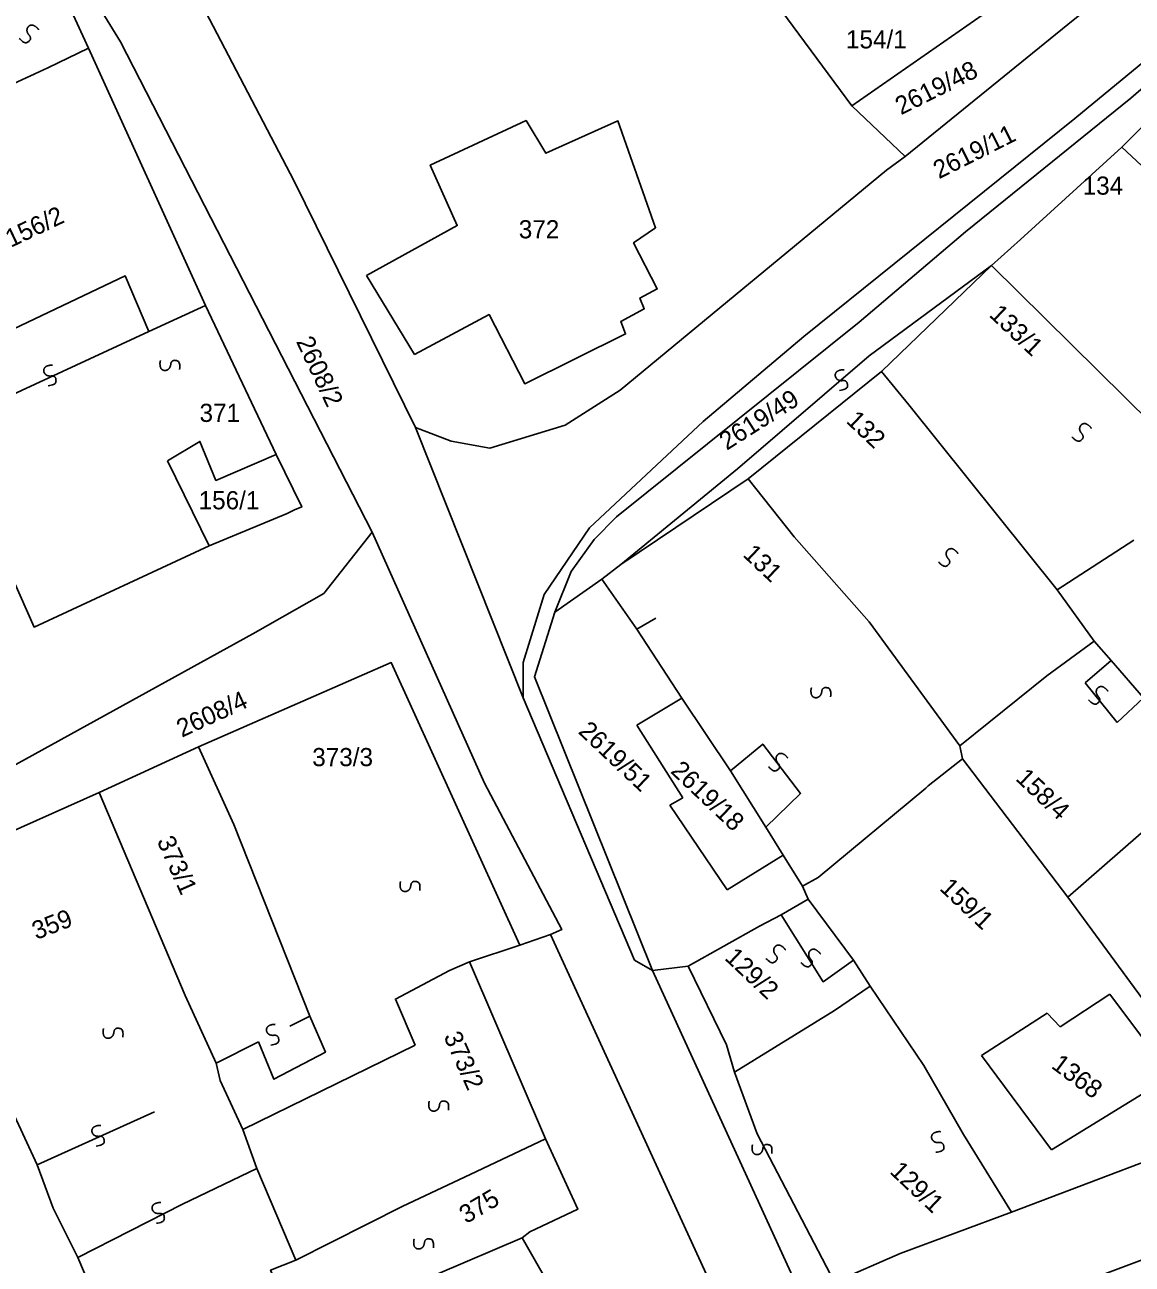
# Model space of a CAD drawing. Extents: x -581999 to -572728, y -1219553 to -1212032.
# Drawn here: x -577580.3 to -577458.4, y -1215689.6 to -1215553.2 of the extents above; entities that cross this region are included whole.
import ezdxf

# ---------------------------------------------------------------- set-up
doc = ezdxf.new("R2010")
doc.units = 0
for name, color, linetype in [('Vrstva 1', 7, 'Continuous'), ('Vrstva 2', 7, 'Continuous'), ('Vrstva 4', 7, 'Continuous'), ('Vrstva 6', 7, 'Continuous')]:
    doc.layers.add(name, color=color, linetype=linetype)

msp = doc.modelspace()

# ---------------------------------------------------------------- linework, layer by layer
at = {"layer": 'Vrstva 1'}
for p, q in [((-577458.52, -1215561.261), (-577448.646, -1215552.634)), ((-577459.515, -1215566.648), (-577447.034, -1215554.113)), ((-577476.745, -1215575.972), (-577458.52, -1215561.261)), ((-577489.259, -1215562.107), (-577483.372, -1215567.684)), ((-577488.453, -1215585.918), (-577476.745, -1215575.972)), ((-577485.982, -1215591.353), (-577473.873, -1215579.702)), ((-577515.182, -1215607.363), (-577488.453, -1215585.918)), ((-577500.672, -1215603.163), (-577485.982, -1215591.353)), ((-577514.699, -1215612.591), (-577500.672, -1215603.163)), ((-577500.672, -1215603.163), (-577495.592, -1215609.547)), ((-577517.611, -1215609.849), (-577515.182, -1215607.363)), ((-577520.152, -1215613.372), (-577517.611, -1215609.849)), ((-577521.967, -1215617.844), (-577520.152, -1215613.372)), ((-577516.777, -1215614.222), (-577514.699, -1215612.591)), ((-577507.962, -1215627.302), (-577512.932, -1215630.306)), ((-577512.932, -1215630.306), (-577507.851, -1215638.283)), ((-577507.851, -1215638.283), (-577509.287, -1215639.112)), ((-577509.287, -1215639.112), (-577502.992, -1215648.436)), ((-577502.992, -1215648.436), (-577496.806, -1215644.603)), ((-577489.076, -1215656.174), (-577494.066, -1215649.44)), ((-577507.266, -1215656.833), (-577503.039, -1215665.479)), ((-577466.299, -1215663.519), (-577460.844, -1215659.907)), ((-577460.844, -1215659.907), (-577454.106, -1215668.936)), ((-577502.157, -1215668.483), (-577491.155, -1215661.717)), ((-577474.962, -1215666.679), (-577467.742, -1215662.014)), ((-577467.742, -1215662.014), (-577466.299, -1215663.519)), ((-577503.039, -1215665.479), (-577502.157, -1215668.483)), ((-577467.261, -1215677.063), (-577474.962, -1215666.679)), ((-577454.106, -1215668.936), (-577467.261, -1215677.063))]:
    msp.add_line(p, q, dxfattribs=at)
for points in [[(-577068.022, -1215163.106), (-577076.012, -1215171.394), (-577092.817, -1215198.932), (-577107.282, -1215215.508), (-577162.965, -1215281.857), (-577201.26, -1215325.168), (-577221.372, -1215346.69), (-577272.951, -1215402.049), (-577277.91, -1215407.931), (-577301.723, -1215433.783), (-577314.534, -1215448.22), (-577343.272, -1215476.19), (-577359.94, -1215491.697), (-577381.842, -1215506.802), (-577421.443, -1215531.966), (-577436.182, -1215542.126), (-577449.269, -1215550.815), (-577464.697, -1215563.514), (-577494.524, -1215587.485), (-577505.622, -1215596.863)], [(-577542.069, -1215609.057), (-577569.787, -1215555.06), (-577595.081, -1215514.025)], [(-577537.306, -1215597.532), (-577533.369, -1215599.008), (-577529.099, -1215599.81), (-577520.833, -1215597.27), (-577514.772, -1215593.393), (-577485.431, -1215569.198), (-577483.372, -1215567.684), (-577465.456, -1215553.156), (-577437.567, -1215530.67), (-577426.685, -1215523.986)], [(-577537.306, -1215597.532), (-577550.668, -1215570.395), (-577570.197, -1215533.019)], [(-577573.298, -1215555.752), (-577579.998, -1215541.197), (-577595.01, -1215547.623)], [(-577474.061, -1215551.543), (-577489.259, -1215562.107), (-577502.181, -1215544.592)], [(-577577.773, -1215557.917), (-577573.298, -1215555.752)], [(-577560.411, -1215584.076), (-577573.298, -1215555.752)], [(-577585.632, -1215564.592), (-577584.028, -1215560.775), (-577577.773, -1215557.917)], [(-577542.695, -1215580.767), (-577532.692, -1215575.284), (-577535.667, -1215568.649), (-577525.12, -1215563.72), (-577522.951, -1215567.317), (-577515.008, -1215563.759), (-577510.857, -1215575.52), (-577513.289, -1215577.205), (-577510.683, -1215582.262), (-577512.594, -1215583.273), (-577512.103, -1215584.469), (-577514.706, -1215585.839), (-577514.166, -1215587.22), (-577525.259, -1215592.698), (-577529.185, -1215585.096), (-577537.406, -1215589.48)], [(-577473.873, -1215579.702), (-577470.68, -1215576.809), (-577459.515, -1215566.648)], [(-577456.256, -1215569.707), (-577459.515, -1215566.648)], [(-577590.029, -1215590.689), (-577569.28, -1215580.813), (-577566.67, -1215586.953)], [(-577537.406, -1215589.48), (-577542.695, -1215580.767)], [(-577473.873, -1215579.702), (-577456.24, -1215597.098)], [(-577566.67, -1215586.953), (-577560.411, -1215584.076)], [(-577552.643, -1215600.488), (-577560.411, -1215584.076)], [(-577485.982, -1215591.353), (-577482.98, -1215595.027)], [(-577482.98, -1215595.027), (-577466.627, -1215615.378)], [(-577587.202, -1215596.462), (-577586.184, -1215603.987), (-577579.3, -1215619.493), (-577560.005, -1215610.562)], [(-577525.457, -1215627.283), (-577525.457, -1215623.406), (-577523.115, -1215615.92), (-577518.156, -1215608.568), (-577505.622, -1215596.863)], [(-577525.457, -1215627.283), (-577537.306, -1215597.532)], [(-577564.597, -1215601.184), (-577561.026, -1215599.06), (-577559.268, -1215603.344), (-577552.643, -1215600.488)], [(-577564.597, -1215601.184), (-577560.005, -1215610.562)], [(-577550.608, -1215606.567), (-577549.817, -1215606.259), (-577552.643, -1215600.488)], [(-577551.432, -1215606.992), (-577550.608, -1215606.567)], [(-577560.005, -1215610.562), (-577551.432, -1215606.992)], [(-577555.196, -1215620.24), (-577547.406, -1215615.791), (-577542.069, -1215609.057)], [(-577542.069, -1215609.057), (-577529.703, -1215636.683)], [(-577495.592, -1215609.547), (-577487.332, -1215618.917), (-577477.371, -1215632.563)], [(-577458.187, -1215609.912), (-577466.627, -1215615.378)], [(-577521.967, -1215617.844), (-577516.777, -1215614.222)], [(-577516.777, -1215614.222), (-577512.932, -1215619.739), (-577507.962, -1215627.302), (-577502.615, -1215635.324)], [(-577466.627, -1215615.378), (-577462.585, -1215621.062)], [(-577511.186, -1215657.294), (-577524.197, -1215624.96), (-577521.967, -1215617.844)], [(-577583.13, -1215635.607), (-577555.196, -1215620.24)], [(-577462.585, -1215621.062), (-577467.774, -1215624.843)], [(-577449.892, -1215635.66), (-577457.154, -1215627.301), (-577460.689, -1215623.157), (-577462.585, -1215621.062)], [(-577561.175, -1215632.674), (-577539.962, -1215623.407), (-577525.817, -1215654.531)], [(-577467.774, -1215624.843), (-577477.371, -1215632.563)], [(-577511.186, -1215657.294), (-577513.197, -1215656.157), (-577525.457, -1215627.283)], [(-577572.129, -1215637.719), (-577561.175, -1215632.674)], [(-577557.293, -1215641.237), (-577561.175, -1215632.674)], [(-577477.371, -1215632.563), (-577477.065, -1215633.989)], [(-577477.065, -1215633.989), (-577480.841, -1215636.983)], [(-577465.471, -1215649.214), (-577477.065, -1215633.989)], [(-577502.615, -1215635.324), (-577498.728, -1215641.51)], [(-577529.703, -1215636.683), (-577521.191, -1215652.805), (-577522.437, -1215653.322)], [(-577449.892, -1215635.66), (-577465.471, -1215649.214)], [(-577572.129, -1215637.719), (-577589.417, -1215645.417)], [(-577562.666, -1215660.071), (-577572.129, -1215637.719)], [(-577480.841, -1215636.983), (-577481.122, -1215637.247), (-577492.957, -1215647.069)], [(-577557.293, -1215641.237), (-577548.925, -1215662.317)], [(-577498.728, -1215641.51), (-577496.806, -1215644.603), (-577494.685, -1215648.013)], [(-577492.957, -1215647.069), (-577494.685, -1215648.013)], [(-577494.685, -1215648.013), (-577494.066, -1215649.44), (-577497.052, -1215651.17)], [(-577465.471, -1215649.214), (-577446.895, -1215674.51)], [(-577497.052, -1215651.17), (-577499.409, -1215652.428)], [(-577499.409, -1215652.428), (-577507.266, -1215656.833)], [(-577522.437, -1215653.322), (-577525.817, -1215654.531)], [(-577522.437, -1215653.322), (-577496.282, -1215710.3)], [(-577525.817, -1215654.531), (-577531.339, -1215656.362)], [(-577531.339, -1215656.362), (-577533.538, -1215657.304)], [(-577522.968, -1215675.854), (-577531.339, -1215656.362)], [(-577507.266, -1215656.833), (-577511.186, -1215657.294)], [(-577487.224, -1215659.039), (-577489.076, -1215656.174)], [(-577533.538, -1215657.304), (-577539.509, -1215660.449), (-577537.339, -1215665.521)], [(-577511.186, -1215657.294), (-577494.758, -1215693.186)], [(-577491.155, -1215661.717), (-577487.224, -1215659.039)], [(-577487.224, -1215659.039), (-577481.314, -1215667.761)], [(-577587.122, -1215661.102), (-577578.944, -1215678.684)], [(-577559.251, -1215667.522), (-577562.666, -1215660.071)], [(-577548.925, -1215662.317), (-577547.219, -1215666.279), (-577552.877, -1215669.268), (-577554.582, -1215665.147)], [(-577554.582, -1215665.147), (-577559.251, -1215667.522)], [(-577537.339, -1215665.521), (-577556.305, -1215674.812)], [(-577558.789, -1215669.422), (-577559.251, -1215667.522)], [(-577481.314, -1215667.761), (-577476.966, -1215675.369)], [(-577556.305, -1215674.812), (-577558.789, -1215669.422)], [(-577554.757, -1215679.089), (-577556.305, -1215674.812)], [(-577446.895, -1215674.51), (-577471.684, -1215683.928)], [(-577531.294, -1215679.782), (-577522.968, -1215675.854)], [(-577522.968, -1215675.854), (-577519.428, -1215683.593), (-577524.702, -1215686.068)], [(-577476.966, -1215675.369), (-577471.684, -1215683.928)], [(-577578.944, -1215678.684), (-577577.205, -1215683.467)], [(-577554.757, -1215679.089), (-577550.462, -1215689.214)], [(-577538.677, -1215683.24), (-577531.294, -1215679.782)], [(-577468.038, -1215693.198), (-577433.831, -1215680.339), (-577425.062, -1215680.368), (-577420.535, -1215682.912), (-577418.354, -1215684.817)], [(-577577.205, -1215683.467), (-577574.478, -1215688.919)], [(-577550.462, -1215689.214), (-577538.677, -1215683.24)], [(-577471.684, -1215683.928), (-577483.925, -1215688.476)], [(-577537.566, -1215691.939), (-577534.847, -1215690.688), (-577525.554, -1215686.729)], [(-577524.702, -1215686.068), (-577525.554, -1215686.729)], [(-577525.554, -1215686.729), (-577521.009, -1215694.714)], [(-577483.925, -1215688.476), (-577491.147, -1215691.616)], [(-577556.264, -1215731.32), (-577565.105, -1215710.887), (-577574.478, -1215688.919)], [(-577550.462, -1215689.214), (-577553.244, -1215690.294), (-577549.88, -1215697.28)]]:
    msp.add_lwpolyline(points, dxfattribs=at)
at = {"layer": 'Vrstva 4'}
for p, q in [((-577487.342, -1215589.629), (-577473.873, -1215579.702)), ((-577501.825, -1215602.083), (-577487.342, -1215589.629)), ((-577510.834, -1215618.496), (-577512.932, -1215619.739)), ((-577460.689, -1215623.157), (-577463.56, -1215625.643)), ((-577463.56, -1215625.643), (-577460.026, -1215629.995)), ((-577460.026, -1215629.995), (-577457.154, -1215627.301)), ((-577499.683, -1215675.295), (-577502.157, -1215668.483)), ((-577491.147, -1215691.616), (-577499.683, -1215675.295))]:
    msp.add_line(p, q, dxfattribs=at)
for points in [[(-577587.202, -1215596.462), (-577566.67, -1215586.953)], [(-577514.699, -1215612.591), (-577501.825, -1215602.083)], [(-577502.615, -1215635.324), (-577499.06, -1215632.378), (-577494.889, -1215637.811), (-577498.728, -1215641.51)], [(-577497.052, -1215651.17), (-577492.426, -1215658.549), (-577489.076, -1215656.174)], [(-577551.125, -1215663.418), (-577548.925, -1215662.317)], [(-577578.944, -1215678.684), (-577566.018, -1215672.881)], [(-577574.478, -1215688.919), (-577562.939, -1215683.047), (-577554.757, -1215679.089)]]:
    msp.add_lwpolyline(points, dxfattribs=at)
at = {"layer": 'Vrstva 6'}
for points in [[(-577580.917, -1215554.68), (-577580.341, -1215555.312), (-577579.699, -1215554.905), (-577579.68, -1215554.499), (-577579.963, -1215554.191), (-577580.093, -1215553.874), (-577580.054, -1215553.576), (-577579.937, -1215553.377), (-577579.721, -1215553.217), (-577579.355, -1215553.2), (-577578.87, -1215553.573), (-577578.79, -1215553.738)], [(-577563.264, -1215591.129), (-577563.169, -1215590.278), (-577563.899, -1215590.066), (-577564.216, -1215590.32), (-577564.261, -1215590.736), (-577564.412, -1215591.043), (-577564.661, -1215591.21), (-577564.888, -1215591.254), (-577565.151, -1215591.198), (-577565.406, -1215590.934), (-577565.446, -1215590.324), (-577565.376, -1215590.155)], [(-577577.76, -1215592.926), (-577576.909, -1215592.837), (-577576.857, -1215592.079), (-577577.173, -1215591.823), (-577577.589, -1215591.868), (-577577.921, -1215591.786), (-577578.138, -1215591.578), (-577578.229, -1215591.366), (-577578.23, -1215591.097), (-577578.027, -1215590.792), (-577577.439, -1215590.622), (-577577.259, -1215590.655)], [(-577490.612, -1215593.437), (-577489.761, -1215593.348), (-577489.709, -1215592.59), (-577490.025, -1215592.334), (-577490.441, -1215592.379), (-577490.773, -1215592.297), (-577490.99, -1215592.089), (-577491.081, -1215591.877), (-577491.082, -1215591.608), (-577490.879, -1215591.303), (-577490.291, -1215591.133), (-577490.111, -1215591.166)], [(-577465.012, -1215598.556), (-577464.436, -1215599.188), (-577463.794, -1215598.781), (-577463.775, -1215598.375), (-577464.058, -1215598.067), (-577464.188, -1215597.75), (-577464.149, -1215597.452), (-577464.032, -1215597.253), (-577463.816, -1215597.093), (-577463.45, -1215597.076), (-577462.965, -1215597.449), (-577462.885, -1215597.614)], [(-577479.706, -1215612.33), (-577479.13, -1215612.962), (-577478.488, -1215612.555), (-577478.469, -1215612.149), (-577478.752, -1215611.841), (-577478.882, -1215611.524), (-577478.843, -1215611.226), (-577478.726, -1215611.027), (-577478.51, -1215610.867), (-577478.144, -1215610.85), (-577477.659, -1215611.223), (-577477.579, -1215611.388)], [(-577491.588, -1215627.16), (-577491.493, -1215626.309), (-577492.223, -1215626.097), (-577492.54, -1215626.351), (-577492.585, -1215626.767), (-577492.736, -1215627.074), (-577492.985, -1215627.241), (-577493.212, -1215627.285), (-577493.475, -1215627.229), (-577493.73, -1215626.965), (-577493.77, -1215626.355), (-577493.7, -1215626.186)], [(-577463.18, -1215627.508), (-577462.604, -1215628.14), (-577461.962, -1215627.733), (-577461.943, -1215627.327), (-577462.226, -1215627.019), (-577462.356, -1215626.702), (-577462.317, -1215626.404), (-577462.2, -1215626.205), (-577461.984, -1215626.045), (-577461.618, -1215626.028), (-577461.133, -1215626.401), (-577461.053, -1215626.566)], [(-577498.436, -1215634.866), (-577497.86, -1215635.498), (-577497.218, -1215635.091), (-577497.199, -1215634.685), (-577497.482, -1215634.377), (-577497.612, -1215634.06), (-577497.573, -1215633.762), (-577497.456, -1215633.563), (-577497.24, -1215633.403), (-577496.874, -1215633.386), (-577496.389, -1215633.759), (-577496.309, -1215633.924)], [(-577536.828, -1215648.495), (-577536.733, -1215647.644), (-577537.463, -1215647.432), (-577537.78, -1215647.686), (-577537.825, -1215648.102), (-577537.976, -1215648.409), (-577538.225, -1215648.576), (-577538.452, -1215648.62), (-577538.715, -1215648.564), (-577538.97, -1215648.3), (-577539.01, -1215647.69), (-577538.94, -1215647.521)], [(-577498.696, -1215655.975), (-577498.12, -1215656.607), (-577497.478, -1215656.2), (-577497.459, -1215655.794), (-577497.742, -1215655.486), (-577497.872, -1215655.169), (-577497.833, -1215654.871), (-577497.716, -1215654.672), (-577497.5, -1215654.512), (-577497.134, -1215654.495), (-577496.649, -1215654.868), (-577496.569, -1215655.033)], [(-577494.845, -1215656.426), (-577494.269, -1215657.058), (-577493.627, -1215656.651), (-577493.608, -1215656.245), (-577493.891, -1215655.937), (-577494.021, -1215655.62), (-577493.982, -1215655.322), (-577493.865, -1215655.123), (-577493.649, -1215654.963), (-577493.283, -1215654.946), (-577492.798, -1215655.319), (-577492.718, -1215655.484)], [(-577569.521, -1215664.657), (-577569.426, -1215663.806), (-577570.156, -1215663.594), (-577570.473, -1215663.848), (-577570.518, -1215664.264), (-577570.669, -1215664.571), (-577570.918, -1215664.738), (-577571.145, -1215664.782), (-577571.408, -1215664.726), (-577571.663, -1215664.462), (-577571.703, -1215663.852), (-577571.633, -1215663.683)], [(-577553.238, -1215665.515), (-577552.387, -1215665.426), (-577552.335, -1215664.668), (-577552.651, -1215664.412), (-577553.067, -1215664.457), (-577553.399, -1215664.375), (-577553.616, -1215664.167), (-577553.707, -1215663.955), (-577553.708, -1215663.686), (-577553.505, -1215663.381), (-577552.917, -1215663.211), (-577552.737, -1215663.244)], [(-577533.669, -1215672.676), (-577533.574, -1215671.825), (-577534.304, -1215671.613), (-577534.621, -1215671.867), (-577534.666, -1215672.283), (-577534.817, -1215672.59), (-577535.066, -1215672.757), (-577535.293, -1215672.801), (-577535.556, -1215672.745), (-577535.811, -1215672.481), (-577535.851, -1215671.871), (-577535.781, -1215671.702)], [(-577572.458, -1215676.635), (-577571.607, -1215676.546), (-577571.555, -1215675.788), (-577571.871, -1215675.532), (-577572.287, -1215675.577), (-577572.619, -1215675.495), (-577572.836, -1215675.287), (-577572.927, -1215675.075), (-577572.928, -1215674.806), (-577572.725, -1215674.501), (-577572.137, -1215674.331), (-577571.957, -1215674.364)], [(-577480.005, -1215677.322), (-577479.154, -1215677.233), (-577479.102, -1215676.475), (-577479.418, -1215676.219), (-577479.834, -1215676.264), (-577480.166, -1215676.182), (-577480.383, -1215675.974), (-577480.474, -1215675.762), (-577480.475, -1215675.493), (-577480.272, -1215675.188), (-577479.684, -1215675.018), (-577479.504, -1215675.051)], [(-577498.067, -1215677.462), (-577497.972, -1215676.611), (-577498.702, -1215676.399), (-577499.019, -1215676.653), (-577499.064, -1215677.069), (-577499.215, -1215677.376), (-577499.464, -1215677.543), (-577499.691, -1215677.587), (-577499.954, -1215677.531), (-577500.209, -1215677.267), (-577500.249, -1215676.657), (-577500.179, -1215676.488)], [(-577565.831, -1215685.13), (-577564.98, -1215685.041), (-577564.928, -1215684.283), (-577565.244, -1215684.027), (-577565.66, -1215684.072), (-577565.992, -1215683.99), (-577566.209, -1215683.782), (-577566.3, -1215683.57), (-577566.301, -1215683.301), (-577566.098, -1215682.996), (-577565.51, -1215682.826), (-577565.33, -1215682.859)], [(-577535.332, -1215687.851), (-577535.237, -1215687), (-577535.967, -1215686.788), (-577536.284, -1215687.042), (-577536.329, -1215687.458), (-577536.48, -1215687.765), (-577536.729, -1215687.932), (-577536.956, -1215687.976), (-577537.219, -1215687.92), (-577537.474, -1215687.656), (-577537.514, -1215687.046), (-577537.444, -1215686.877)]]:
    msp.add_open_spline(points, degree=2, dxfattribs=at)

# ---------------------------------------------------------------- texts
at = {"layer": 'Vrstva 2'}
for s, p in [('154/1', (-577489.902, -1215555.784)), ('134', (-577463.837, -1215571.888)), ('372', (-577525.925, -1215576.693)), ('371', (-577561.075, -1215596.907)), ('156/1', (-577561.176, -1215606.529)), ('373/3', (-577548.667, -1215634.808))]:
    msp.add_text(s, height=2, dxfattribs=at).set_placement(p)
for s, rotation, p in [('2619/48', 26.59871, (-577483.836, -1215563.157)), ('2619/11', 26.59871, (-577479.657, -1215570.192)), ('156/2', 25.35313, (-577581.849, -1215577.74)), ('133/1', 316.61133, (-577474.235, -1215585.217)), ('2608/2', 295.31046, (-577550.48, -1215588.047)), ('2619/49', 32.4835, (-577503.026, -1215600.09)), ('132', 316.61133, (-577489.983, -1215596.905)), ('131', 316.61133, (-577501.355, -1215611.62)), ('2608/4', 24.79736, (-577563.022, -1215631.681)), ('2619/51', 316.61133, (-577519.471, -1215631.107)), ('2619/18', 316.61133, (-577509.306, -1215635.464)), ('158/4', 316.61133, (-577471.315, -1215636.283)), ('373/1', 294.0509, (-577565.807, -1215643.026)), ('159/1', 316.61133, (-577479.693, -1215648.359)), ('359', 21.05858, (-577579.047, -1215653.946)), ('129/2', 316.61133, (-577503.362, -1215656.025)), ('373/2', 294.0509, (-577534.235, -1215664.551)), ('1368', 323.23514, (-577467.401, -1215667.958)), ('129/1', 316.61133, (-577485.176, -1215679.549)), ('375', 30.45336, (-577531.724, -1215685.238))]:
    msp.add_text(s, height=2, rotation=rotation, dxfattribs=at).set_placement(p)

doc.saveas('drawing.dxf')
